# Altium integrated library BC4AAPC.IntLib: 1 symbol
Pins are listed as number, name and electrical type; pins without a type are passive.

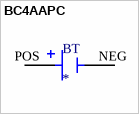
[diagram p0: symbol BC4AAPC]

## BC4AAPC
designator BT
BATTERY HOLDER AA 4 CELL PC PIN; MF: MPD; MP: BC4AAPC
footprint BAT_BC4AAPC
pins: NEG, POS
